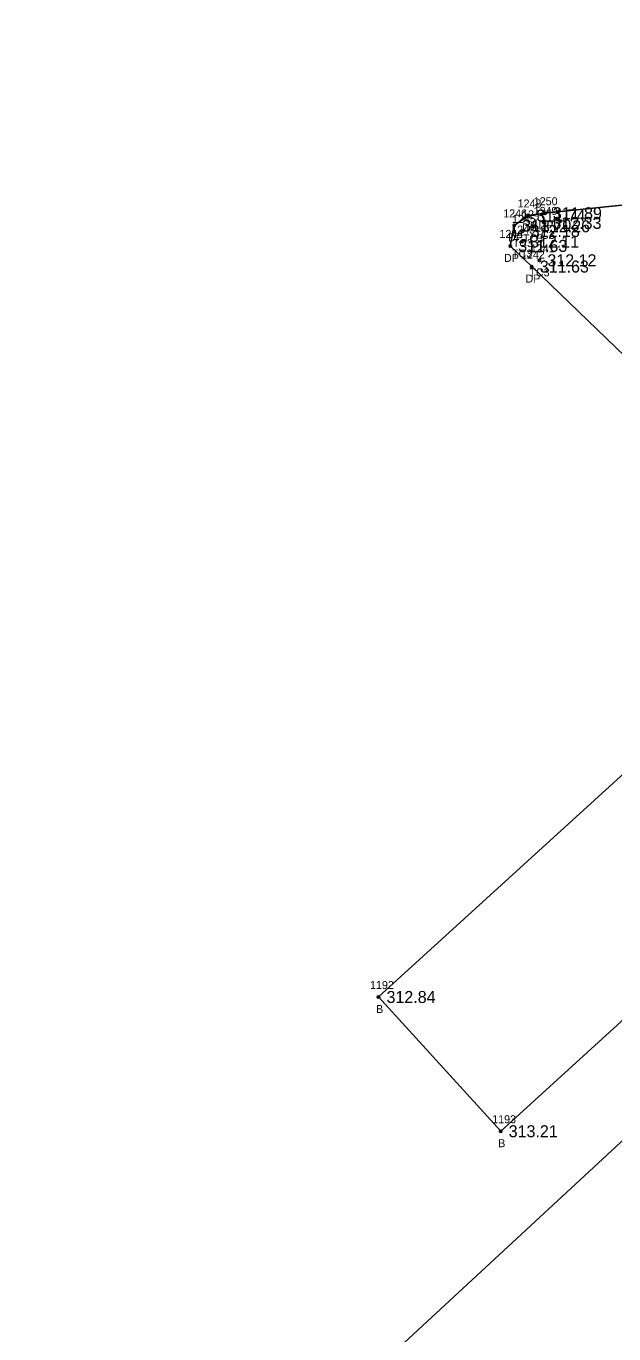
# Model space of a CAD drawing. Extents: x 1970076 to 1971136, y 803126 to 804215.
# Drawn here: x 1970663.4 to 1970736.9, y 803214.9 to 803378.3 of the extents above; entities that cross this region are included whole.
import ezdxf

# ---------------------------------------------------------------- set-up
doc = ezdxf.new("R2010")
doc.units = 0
for name, color, linetype in [('RD_EX_Bldg', 7, 'Continuous'), ('RD_EX_Bldg_txCode', 7, 'Continuous'), ('RD_EX_Conc_txCode', 7, 'Continuous'), ('RD_EX_Driveway', 7, 'Continuous'), ('RD_EX_Driveway_txCode', 7, 'Continuous'), ('RD_EX_TX_Bldg_ELEV', 7, 'Continuous'), ('RD_EX_TX_Conc_ELEV', 7, 'Continuous'), ('RD_EX_TX_Driveway_ELEV', 7, 'Continuous'), ('RD_SMD_Locator', 7, 'Continuous')]:
    doc.layers.add(name, color=color, linetype=linetype)

msp = doc.modelspace()

# ---------------------------------------------------------------- linework, layer by layer
at = {"layer": 'RD_EX_Bldg'}
for points in [[(1970781.9, 803294.06), (1970766.62, 803310.84), (1970707.47, 803256.98), (1970722.75, 803240.2), (1970781.9, 803294.06)], [(1970698.2, 803132.22), (1970763.48, 803192.62), (1970767.27, 803189.39), (1970829.69, 803248.82), (1970792.38, 803289.36), (1970663.41, 803170.02), (1970698.2, 803132.22)]]:
    msp.add_lwpolyline(points, dxfattribs=at)
at = {"layer": 'RD_EX_Driveway'}
msp.add_lwpolyline([(1970741.85, 803306.21), (1970781.95, 803343.87), (1970771.39, 803355.03), (1970767.69, 803353.46), (1970750.32, 803337.06), (1970748.77, 803333.34), (1970745.86, 803331.64), (1970742.99, 803332.53), (1970726.64, 803348.27), (1970723.94, 803350.85), (1970724.44, 803353.41), (1970726.22, 803354.65), (1970728.27, 803354.93), (1970747.47, 803356.95), (1970751.34, 803358.22), (1970755.32, 803360.5), (1970757.62, 803362.13), (1970759.65, 803363.71), (1970739.14, 803382.97)], dxfattribs=at)
at = {"layer": 'RD_SMD_Locator'}
for centre in [(1970726.22, 803354.65), (1970728.22, 803353.72), (1970728.27, 803354.93), (1970724.44, 803353.41), (1970725.5, 803352.71), (1970726.78, 803353.3), (1970723.94, 803350.85), (1970725.42, 803351.39), (1970727.59, 803349.05), (1970726.64, 803348.27), (1970707.47, 803256.98), (1970722.75, 803240.2)]:
    msp.add_circle(centre, 0.15, dxfattribs=at)

# ---------------------------------------------------------------- texts
at = {"layer": 'RD_EX_Bldg_txCode'}
for s, p in [('1192', (1970706.41, 803257.98)), ('B', (1970707.16, 803254.98)), ('1193', (1970721.69, 803241.2)), ('B', (1970722.44, 803238.2))]:
    msp.add_text(s, height=1, dxfattribs=at).set_placement(p)
at = {"layer": 'RD_EX_Conc_txCode'}
for s, p in [('1249', (1970726.87, 803354.72)), ('1245', (1970724.16, 803353.71)), ('1247', (1970725.43, 803354.3)), ('1243', (1970724.07, 803352.39)), ('TC3', (1970725.54, 803351.3)), ('TC3', (1970726.97, 803351.72)), ('TC3', (1970724.26, 803350.71)), ('1241', (1970726.52, 803350.05)), ('TC3', (1970724.17, 803349.39)), ('TC3', (1970726.34, 803347.05))]:
    msp.add_text(s, height=1, dxfattribs=at).set_placement(p)
at = {"layer": 'RD_EX_Driveway_txCode'}
for s, p in [('1248', (1970724.87, 803355.65)), ('1250', (1970726.89, 803355.93)), ('1246', (1970723.07, 803354.41)), ('DP', (1970727.49, 803352.93)), ('1244', (1970722.6, 803351.85)), ('DP', (1970723.66, 803351.41)), ('DP', (1970725.44, 803352.65)), ('DP', (1970723.16, 803348.85)), ('1242', (1970725.29, 803349.27)), ('DP', (1970725.86, 803346.27))]:
    msp.add_text(s, height=1, dxfattribs=at).set_placement(p)
at = {"layer": 'RD_EX_TX_Bldg_ELEV'}
for s, p in [('312.84', (1970708.47, 803256.23)), ('313.21', (1970723.75, 803239.45))]:
    msp.add_text(s, height=1.5, dxfattribs=at).set_placement(p)
at = {"layer": 'RD_EX_TX_Conc_ELEV'}
for s, p in [('312.26', (1970727.78, 803352.55)), ('312.33', (1970729.22, 803352.97)), ('312.18', (1970726.5, 803351.96)), ('312.11', (1970726.42, 803350.64)), ('312.12', (1970728.59, 803348.3))]:
    msp.add_text(s, height=1.5, dxfattribs=at).set_placement(p)
at = {"layer": 'RD_EX_TX_Driveway_ELEV'}
for s, p in [('311.89', (1970729.27, 803354.18)), ('311.70', (1970725.44, 803352.66)), ('311.74', (1970727.22, 803353.9)), ('311.63', (1970724.94, 803350.1)), ('311.63', (1970727.64, 803347.52))]:
    msp.add_text(s, height=1.5, dxfattribs=at).set_placement(p)

doc.saveas('drawing.dxf')
